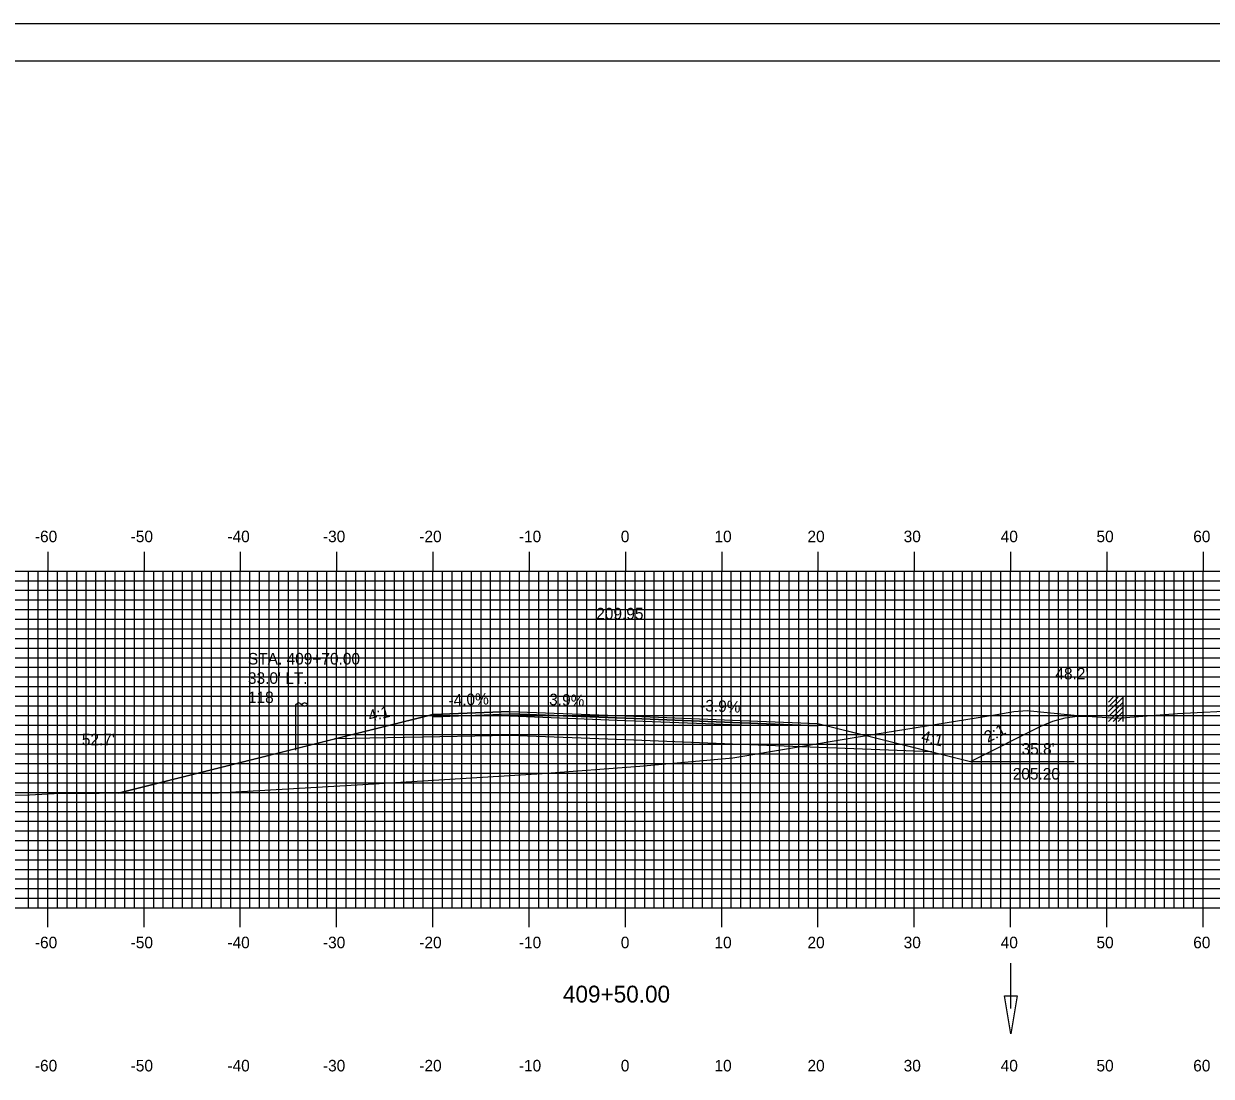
# Model space of a CAD drawing. Extents: x 852922 to 853266, y 364785 to 365005.
# Drawn here: x 853025.7 to 853149.1, y 364895.7 to 365005.1 of the extents above; entities that cross this region are included whole.
import ezdxf

# ---------------------------------------------------------------- set-up
doc = ezdxf.new("R2010")
doc.units = 0
for name, color, linetype in [('ANNOTATION', 7, 'Continuous'), ('BORDER', 7, 'Continuous'), ('D_Drainage_Ditch_Line', 7, 'Continuous'), ('D_Drainage_Text', 7, 'Continuous'), ('D_Roadway_Centerline', 7, 'Continuous'), ('D_Roadway_Centerline_Text', 7, 'Continuous'), ('D_Roadway_Edge_Shoulder', 7, 'Continuous'), ('D_Roadway_Edge_TW', 7, 'Continuous'), ('D_Roadway_Pavement', 7, 'Continuous'), ('D_Roadway_SlopeLines', 7, 'Continuous'), ('D_Roadway_SubGrade', 7, 'Continuous'), ('D_Text_Standard', 7, 'Continuous'), ('D_Utilities_Pole_Joint', 7, 'Continuous'), ('H_V ANNOTATION', 7, 'Continuous'), ('M_Buildings_Rooftop', 7, 'Continuous'), ('MAJOR', 7, 'Continuous'), ('MINOR', 7, 'Continuous'), ('PDRAIN', 7, 'Continuous'), ('PLOT BOUNDARY', 7, 'Continuous'), ('S_Roadway_Centerline', 7, 'Continuous')]:
    doc.layers.add(name, color=color, linetype=linetype)

msp = doc.modelspace()

# ---------------------------------------------------------------- linework, layer by layer
at = {"layer": 'BORDER'}
msp.add_lwpolyline([(852938.64, 364791.23), (853258.64, 364791.23), (853258.64, 365001.23), (852938.64, 365001.23)], close=True, dxfattribs=at)
at = {"layer": 'D_Drainage_Ditch_Line'}
msp.add_line((853128.26, 364902.77), (853128.26, 364907.47), dxfattribs=at)
msp.add_lwpolyline([(853127.6, 364904.09), (853128.92, 364904.09), (853128.26, 364900.15)], close=True, dxfattribs=at)
at = {"layer": 'D_Roadway_Centerline'}
msp.add_lwpolyline([(853035.55, 364925.16), (853056.24, 364930.33), (853058.07, 364930.79), (853068.24, 364933.33), (853076.24, 364933.65), (853088.24, 364933.18), (853100.24, 364932.71), (853108.24, 364932.39), (853120.08, 364929.43), (853124.08, 364928.43), (853131.4, 364932.1), (853132.65, 364932.63), (853133.9, 364932.98), (853135.15, 364933.15), (853136.4, 364933.14)], dxfattribs=at)
at = {"layer": 'D_Roadway_Edge_Shoulder'}
for points in [[(853076.24, 364933.65), (853068.24, 364933.33), (853068.24, 364933.08), (853076.24, 364933.4)], [(853100.24, 364932.71), (853108.24, 364932.39), (853108.24, 364932.14), (853100.24, 364932.46)]]:
    msp.add_lwpolyline(points, close=True, dxfattribs=at)
at = {"layer": 'D_Roadway_Edge_TW'}
msp.add_lwpolyline([(853076.24, 364933.4), (853076.24, 364933.65), (853088.24, 364933.18), (853100.24, 364932.71), (853100.24, 364932.46), (853088.24, 364932.93)], close=True, dxfattribs=at)
at = {"layer": 'D_Roadway_Pavement'}
msp.add_lwpolyline([(853076.24, 364933.15), (853076.24, 364933.4), (853088.24, 364932.93), (853100.24, 364932.46), (853100.24, 364932.21), (853088.24, 364932.68)], close=True, dxfattribs=at)
at = {"layer": 'D_Roadway_SlopeLines'}
for points in [[(853068.24, 364933.33), (853035.55, 364925.16)], [(853124.08, 364928.43), (853131.4, 364932.1), (853132.65, 364932.63), (853133.9, 364932.98), (853135.15, 364933.15), (853136.4, 364933.14)], [(853108.24, 364932.39), (853124.08, 364928.43)]]:
    msp.add_lwpolyline(points, dxfattribs=at)
at = {"layer": 'D_Roadway_SubGrade'}
msp.add_lwpolyline([(853076.24, 364931.15), (853058.07, 364930.79), (853068.24, 364933.33), (853068.24, 364933.08), (853076.24, 364933.4), (853088.24, 364932.93), (853100.24, 364932.46), (853108.24, 364932.14), (853108.24, 364932.39), (853120.08, 364929.43), (853100.24, 364930.21), (853088.24, 364930.68)], close=True, dxfattribs=at)
at = {"layer": 'D_Utilities_Pole_Joint'}
for p, q in [((853053.99, 364934.36), (853054.15, 364934.47)), ((853053.99, 364929.6), (853053.99, 364934.36)), ((853054.46, 364934.47), (853054.62, 364934.36)), ((853054.77, 364934.47), (853054.62, 364934.36)), ((853054.62, 364934.36), (853054.77, 364934.24)), ((853055.24, 364934.36), (853055.09, 364934.47)), ((853055.09, 364934.24), (853055.24, 364934.36)), ((853055.24, 364929.6), (853055.24, 364934.36))]:
    msp.add_line(p, q, dxfattribs=at)
for centre, start, end in [((853054.31, 364934.25), 90, 125.2644), ((853054.31, 364934.25), 54.7356, 90), ((853054.93, 364934.25), 90, 125.2644), ((853054.93, 364934.47), 234.7356, 270), ((853054.93, 364934.25), 54.7356, 90), ((853054.93, 364934.47), 270, 305.2644)]:
    msp.add_arc(centre, 0.271, start, end, dxfattribs=at)
at = {"layer": 'M_Buildings_Rooftop'}
for p, q in [((853138.43, 364933.63), (853139.94, 364935.13)), ((853138.43, 364934.12), (853139.41, 364935.13)), ((853138.43, 364934.61), (853138.92, 364935.13)), ((853138.43, 364933.13), (853139.94, 364934.61)), ((853139.94, 364932.61), (853139.94, 364935.13)), ((853138.43, 364932.61), (853139.94, 364934.12)), ((853138.92, 364932.61), (853139.94, 364933.63)), ((853139.41, 364932.61), (853139.94, 364933.13))]:
    msp.add_line(p, q, dxfattribs=at)
at = {"layer": 'MAJOR'}
for p, q in [((853028.24, 364950.24), (853028.24, 364948.23)), ((853038.24, 364950.24), (853038.24, 364948.23)), ((853048.24, 364950.24), (853048.24, 364948.23)), ((853058.24, 364950.24), (853058.24, 364948.23)), ((853068.24, 364950.24), (853068.24, 364948.23)), ((853078.24, 364950.24), (853078.24, 364948.23)), ((853088.24, 364950.24), (853088.24, 364948.23)), ((853098.24, 364950.24), (853098.24, 364948.23)), ((853108.24, 364950.24), (853108.24, 364948.23)), ((853118.24, 364950.24), (853118.24, 364948.23)), ((853128.24, 364950.24), (853128.24, 364948.23)), ((853138.24, 364950.24), (853138.24, 364948.23)), ((853148.24, 364950.24), (853148.24, 364948.23)), ((852948.24, 364948.23), (853228.24, 364948.23)), ((852948.24, 364948.23), (853228.24, 364948.23)), ((853028.24, 364913.23), (853028.24, 364948.23)), ((853038.24, 364913.23), (853038.24, 364948.23)), ((853048.24, 364913.23), (853048.24, 364948.23)), ((853058.24, 364913.23), (853058.24, 364948.23)), ((853068.24, 364913.23), (853068.24, 364948.23)), ((853078.24, 364913.23), (853078.24, 364948.23)), ((853088.24, 364913.23), (853088.24, 364948.23)), ((853098.24, 364913.23), (853098.24, 364948.23)), ((853108.24, 364913.23), (853108.24, 364948.23)), ((853118.24, 364913.23), (853118.24, 364948.23)), ((853128.24, 364913.23), (853128.24, 364948.23)), ((853138.24, 364913.23), (853138.24, 364948.23)), ((853148.24, 364913.23), (853148.24, 364948.23)), ((852948.24, 364943.23), (853228.24, 364943.23)), ((852948.24, 364938.23), (853228.24, 364938.23)), ((852948.24, 364933.23), (853228.24, 364933.23)), ((852948.24, 364928.23), (853228.24, 364928.23)), ((852948.24, 364923.23), (853228.24, 364923.23)), ((852948.24, 364918.23), (853228.24, 364918.23)), ((852948.24, 364913.23), (853228.24, 364913.23)), ((852948.24, 364913.23), (853228.24, 364913.23)), ((853028.24, 364911.23), (853028.24, 364913.23)), ((853038.24, 364911.23), (853038.24, 364913.23)), ((853048.24, 364911.23), (853048.24, 364913.23)), ((853058.24, 364911.23), (853058.24, 364913.23)), ((853068.24, 364911.23), (853068.24, 364913.23)), ((853078.24, 364911.23), (853078.24, 364913.23)), ((853088.24, 364911.23), (853088.24, 364913.23)), ((853098.24, 364911.23), (853098.24, 364913.23)), ((853108.24, 364911.23), (853108.24, 364913.23)), ((853118.24, 364911.23), (853118.24, 364913.23)), ((853128.24, 364911.23), (853128.24, 364913.23)), ((853138.24, 364911.23), (853138.24, 364913.23)), ((853148.24, 364911.23), (853148.24, 364913.23))]:
    msp.add_line(p, q, dxfattribs=at)
at = {"layer": 'MINOR'}
for p, q in [((853026.24, 364913.23), (853026.24, 364948.23)), ((853027.24, 364913.23), (853027.24, 364948.23)), ((853029.24, 364913.23), (853029.24, 364948.23)), ((853030.24, 364913.23), (853030.24, 364948.23)), ((853031.24, 364913.23), (853031.24, 364948.23)), ((853032.24, 364913.23), (853032.24, 364948.23)), ((853033.24, 364913.23), (853033.24, 364948.23)), ((853034.24, 364913.23), (853034.24, 364948.23)), ((853035.24, 364913.23), (853035.24, 364948.23)), ((853036.24, 364913.23), (853036.24, 364948.23)), ((853037.24, 364913.23), (853037.24, 364948.23)), ((853039.24, 364913.23), (853039.24, 364948.23)), ((853040.24, 364913.23), (853040.24, 364948.23)), ((853041.24, 364913.23), (853041.24, 364948.23)), ((853042.24, 364913.23), (853042.24, 364948.23)), ((853043.24, 364913.23), (853043.24, 364948.23)), ((853044.24, 364913.23), (853044.24, 364948.23)), ((853045.24, 364913.23), (853045.24, 364948.23)), ((853046.24, 364913.23), (853046.24, 364948.23)), ((853047.24, 364913.23), (853047.24, 364948.23)), ((853049.24, 364913.23), (853049.24, 364948.23)), ((853050.24, 364913.23), (853050.24, 364948.23)), ((853051.24, 364913.23), (853051.24, 364948.23)), ((853052.24, 364913.23), (853052.24, 364948.23)), ((853053.24, 364913.23), (853053.24, 364948.23)), ((853054.24, 364913.23), (853054.24, 364948.23)), ((853055.24, 364913.23), (853055.24, 364948.23)), ((853056.24, 364913.23), (853056.24, 364948.23)), ((853057.24, 364913.23), (853057.24, 364948.23)), ((853059.24, 364913.23), (853059.24, 364948.23)), ((853060.24, 364913.23), (853060.24, 364948.23)), ((853061.24, 364913.23), (853061.24, 364948.23)), ((853062.24, 364913.23), (853062.24, 364948.23)), ((853063.24, 364913.23), (853063.24, 364948.23)), ((853064.24, 364913.23), (853064.24, 364948.23)), ((853065.24, 364913.23), (853065.24, 364948.23)), ((853066.24, 364913.23), (853066.24, 364948.23)), ((853067.24, 364913.23), (853067.24, 364948.23)), ((853069.24, 364913.23), (853069.24, 364948.23)), ((853070.24, 364913.23), (853070.24, 364948.23)), ((853071.24, 364913.23), (853071.24, 364948.23)), ((853072.24, 364913.23), (853072.24, 364948.23)), ((853073.24, 364913.23), (853073.24, 364948.23)), ((853074.24, 364913.23), (853074.24, 364948.23)), ((853075.24, 364913.23), (853075.24, 364948.23)), ((853076.24, 364913.23), (853076.24, 364948.23)), ((853077.24, 364913.23), (853077.24, 364948.23)), ((853079.24, 364913.23), (853079.24, 364948.23)), ((853080.24, 364913.23), (853080.24, 364948.23)), ((853081.24, 364913.23), (853081.24, 364948.23)), ((853082.24, 364913.23), (853082.24, 364948.23)), ((853083.24, 364913.23), (853083.24, 364948.23)), ((853084.24, 364913.23), (853084.24, 364948.23)), ((853085.24, 364913.23), (853085.24, 364948.23)), ((853086.24, 364913.23), (853086.24, 364948.23)), ((853087.24, 364913.23), (853087.24, 364948.23)), ((853089.24, 364913.23), (853089.24, 364948.23)), ((853090.24, 364913.23), (853090.24, 364948.23)), ((853091.24, 364913.23), (853091.24, 364948.23)), ((853092.24, 364913.23), (853092.24, 364948.23)), ((853093.24, 364913.23), (853093.24, 364948.23)), ((853094.24, 364913.23), (853094.24, 364948.23)), ((853095.24, 364913.23), (853095.24, 364948.23)), ((853096.24, 364913.23), (853096.24, 364948.23)), ((853097.24, 364913.23), (853097.24, 364948.23)), ((853099.24, 364913.23), (853099.24, 364948.23)), ((853100.24, 364913.23), (853100.24, 364948.23)), ((853101.24, 364913.23), (853101.24, 364948.23)), ((853102.24, 364913.23), (853102.24, 364948.23)), ((853103.24, 364913.23), (853103.24, 364948.23)), ((853104.24, 364913.23), (853104.24, 364948.23)), ((853105.24, 364913.23), (853105.24, 364948.23)), ((853106.24, 364913.23), (853106.24, 364948.23)), ((853107.24, 364913.23), (853107.24, 364948.23)), ((853109.24, 364913.23), (853109.24, 364948.23)), ((853110.24, 364913.23), (853110.24, 364948.23)), ((853111.24, 364913.23), (853111.24, 364948.23)), ((853112.24, 364913.23), (853112.24, 364948.23)), ((853113.24, 364913.23), (853113.24, 364948.23)), ((853114.24, 364913.23), (853114.24, 364948.23)), ((853115.24, 364913.23), (853115.24, 364948.23)), ((853116.24, 364913.23), (853116.24, 364948.23)), ((853117.24, 364913.23), (853117.24, 364948.23)), ((853119.24, 364913.23), (853119.24, 364948.23)), ((853120.24, 364913.23), (853120.24, 364948.23)), ((853121.24, 364913.23), (853121.24, 364948.23)), ((853122.24, 364913.23), (853122.24, 364948.23)), ((853123.24, 364913.23), (853123.24, 364948.23)), ((853124.24, 364913.23), (853124.24, 364948.23)), ((853125.24, 364913.23), (853125.24, 364948.23)), ((853126.24, 364913.23), (853126.24, 364948.23)), ((853127.24, 364913.23), (853127.24, 364948.23)), ((853129.24, 364913.23), (853129.24, 364948.23)), ((853130.24, 364913.23), (853130.24, 364948.23)), ((853131.24, 364913.23), (853131.24, 364948.23)), ((853132.24, 364913.23), (853132.24, 364948.23)), ((853133.24, 364913.23), (853133.24, 364948.23)), ((853134.24, 364913.23), (853134.24, 364948.23)), ((853135.24, 364913.23), (853135.24, 364948.23)), ((853136.24, 364913.23), (853136.24, 364948.23)), ((853137.24, 364913.23), (853137.24, 364948.23)), ((853139.24, 364913.23), (853139.24, 364948.23)), ((853140.24, 364913.23), (853140.24, 364948.23)), ((853141.24, 364913.23), (853141.24, 364948.23)), ((853142.24, 364913.23), (853142.24, 364948.23)), ((853143.24, 364913.23), (853143.24, 364948.23)), ((853144.24, 364913.23), (853144.24, 364948.23)), ((853145.24, 364913.23), (853145.24, 364948.23)), ((853146.24, 364913.23), (853146.24, 364948.23)), ((853147.24, 364913.23), (853147.24, 364948.23)), ((852948.24, 364947.23), (853228.24, 364947.23)), ((852948.24, 364946.23), (853228.24, 364946.23)), ((852948.24, 364945.23), (853228.24, 364945.23)), ((852948.24, 364944.23), (853228.24, 364944.23)), ((852948.24, 364942.23), (853228.24, 364942.23)), ((852948.24, 364941.23), (853228.24, 364941.23)), ((852948.24, 364940.23), (853228.24, 364940.23)), ((852948.24, 364939.23), (853228.24, 364939.23)), ((852948.24, 364937.23), (853228.24, 364937.23)), ((852948.24, 364936.23), (853228.24, 364936.23)), ((852948.24, 364935.23), (853228.24, 364935.23)), ((852948.24, 364934.23), (853228.24, 364934.23)), ((852948.24, 364932.23), (853228.24, 364932.23)), ((852948.24, 364931.23), (853228.24, 364931.23)), ((852948.24, 364930.23), (853228.24, 364930.23)), ((852948.24, 364929.23), (853228.24, 364929.23)), ((852948.24, 364927.23), (853228.24, 364927.23)), ((852948.24, 364926.23), (853228.24, 364926.23)), ((852948.24, 364925.23), (853228.24, 364925.23)), ((852948.24, 364924.23), (853228.24, 364924.23)), ((852948.24, 364922.23), (853228.24, 364922.23)), ((852948.24, 364921.23), (853228.24, 364921.23)), ((852948.24, 364920.23), (853228.24, 364920.23)), ((852948.24, 364919.23), (853228.24, 364919.23)), ((852948.24, 364917.23), (853228.24, 364917.23)), ((852948.24, 364916.23), (853228.24, 364916.23)), ((852948.24, 364915.23), (853228.24, 364915.23)), ((852948.24, 364914.23), (853228.24, 364914.23))]:
    msp.add_line(p, q, dxfattribs=at)
at = {"layer": 'PDRAIN'}
msp.add_line((853124.08, 364928.43), (853134.85, 364928.43), dxfattribs=at)
at = {"layer": 'PLOT BOUNDARY'}
msp.add_lwpolyline([(852922.46, 364785.11), (853262.46, 364785.11), (853262.46, 365005.11), (852922.46, 365005.11)], close=True, dxfattribs=at)
at = {"layer": 'S_Roadway_Centerline'}
msp.add_lwpolyline([(853012.97, 364924.81), (853026.35, 364924.97), (853029.53, 364925.14), (853033.59, 364925.16), (853045.96, 364925.18), (853060.97, 364926.05), (853079.6, 364927.19), (853089.74, 364927.97), (853099.41, 364928.82), (853112.01, 364930.93), (853126.83, 364933.33), (853128.58, 364933.62), (853129.98, 364933.75), (853135.19, 364933.22), (853139.27, 364932.95), (853145.58, 364933.42), (853152.41, 364933.77)], dxfattribs=at)

# ---------------------------------------------------------------- texts
at = {"layer": 'ANNOTATION'}
for s, rotation, p in [('-4.0%', 2.2906, (853069.88, 364934.2)), ('3.9%', 357.7534, (853080.3, 364934.3)), ('4:1', 14.0362, (853061.69, 364932.56)), ('-3.9%', 357.7358, (853095.98, 364933.68)), ('2:1', 26.5651, (853125.88, 364930.37)), ('4:1', 345.9638, (853118.9, 364930.54))]:
    msp.add_text(s, height=1.2, rotation=rotation, dxfattribs=at).set_placement(p)
for s, p in [("35.8'", (853129.39, 364929.16)), ('205.20', (853128.47, 364926.56))]:
    msp.add_text(s, height=1.2, dxfattribs=at).set_placement(p)
at = {"layer": 'D_Drainage_Text'}
for s, p in [('STA. 409+70.00', (853049.03, 364938.52)), ("33.0' LT.", (853049.03, 364936.51)), ('118', (853049.03, 364934.51))]:
    msp.add_text(s, height=1.2, dxfattribs=at).set_placement(p)
at = {"layer": 'D_Roadway_Centerline'}
for s in ['C', 'L']:
    msp.add_text(s, height=0.0146, dxfattribs=at).set_placement((853088.24, 364933.18))
at = {"layer": 'D_Roadway_Centerline_Text'}
msp.add_text('209.95', height=1.2, dxfattribs=at).set_placement((853085.21, 364943.21))
at = {"layer": 'D_Text_Standard'}
for s, p in [("48.2'", (853132.9, 364936.97)), ("52.7'", (853031.78, 364930.13))]:
    msp.add_text(s, height=1.2, dxfattribs=at).set_placement(p)
at = {"layer": 'H_V ANNOTATION'}
for s, height, p in [('-60', 1.2, (853026.9, 364951.23)), ('-50', 1.2, (853036.85, 364951.23)), ('-40', 1.2, (853046.9, 364951.23)), ('-30', 1.2, (853056.82, 364951.23)), ('-20', 1.2, (853066.83, 364951.23)), ('-10', 1.2, (853077.17, 364951.23)), ('0', 1.2, (853087.76, 364951.23)), ('10', 1.2, (853097.49, 364951.23)), ('20', 1.2, (853107.15, 364951.23)), ('30', 1.2, (853117.14, 364951.23)), ('40', 1.2, (853127.22, 364951.23)), ('50', 1.2, (853137.17, 364951.23)), ('60', 1.2, (853147.22, 364951.23)), ('-60', 1.2, (853026.9, 364909.03)), ('-50', 1.2, (853036.85, 364909.03)), ('-40', 1.2, (853046.9, 364909.03)), ('-30', 1.2, (853056.82, 364909.03)), ('-20', 1.2, (853066.83, 364909.03)), ('-10', 1.2, (853077.17, 364909.03)), ('0', 1.2, (853087.76, 364909.03)), ('10', 1.2, (853097.49, 364909.03)), ('20', 1.2, (853107.15, 364909.03)), ('30', 1.2, (853117.14, 364909.03)), ('40', 1.2, (853127.22, 364909.03)), ('50', 1.2, (853137.17, 364909.03)), ('60', 1.2, (853147.22, 364909.03)), ('409+50.00', 1.75, (853081.75, 364903.39)), ('-60', 1.2, (853026.9, 364896.23)), ('-50', 1.2, (853036.85, 364896.23)), ('-40', 1.2, (853046.9, 364896.23)), ('-30', 1.2, (853056.82, 364896.23)), ('-20', 1.2, (853066.83, 364896.23)), ('-10', 1.2, (853077.17, 364896.23)), ('0', 1.2, (853087.76, 364896.23)), ('10', 1.2, (853097.49, 364896.23)), ('20', 1.2, (853107.15, 364896.23)), ('30', 1.2, (853117.14, 364896.23)), ('40', 1.2, (853127.22, 364896.23)), ('50', 1.2, (853137.17, 364896.23)), ('60', 1.2, (853147.22, 364896.23))]:
    msp.add_text(s, height=height, dxfattribs=at).set_placement(p)

doc.saveas('drawing.dxf')
